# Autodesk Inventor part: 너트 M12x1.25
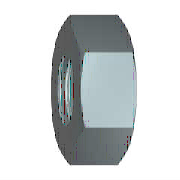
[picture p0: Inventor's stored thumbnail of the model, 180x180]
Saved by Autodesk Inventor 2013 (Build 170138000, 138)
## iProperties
IsCustomPart: 1
Created: 2012-02
Part Number: 너트 M12x1.25
Material: 강철, 연강
Description: 6각 너트
Document SubType Name: Modeling
Standard: KS B 1012
Designer: mduedu
Standards Organization: KS
Language: ko-KR
Size Designation: M12x1.25
Categories: <MemberInstance><Categories><Category DisplayName="조임쇠" InternalName="e4da775c-781d-43d5-af7c-5136215cf5a6" Mnemonic="FSTN"><Category DisplayName="너트" InternalN
Density: 1 g/cm^3
Author: mduedu
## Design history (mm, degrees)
sketch "스케치1"
  geometry: L1 (-10.97, 0)-(-5.485, 9.5); L2 (-5.485, 9.5)-(5.485, 9.5); L3 (5.485, 9.5)-(10.97, 0); L4 (10.97, 0)-(5.485, -9.5); L5 (5.485, -9.5)-(-5.485, -9.5); L6 (-5.485, -9.5)-(-10.97, 0); 2 further points
  constraints: 12 end point, 1 coincident, 1 horizontal, 11 other
  dimensions: "d0" = 21.93931 distance of L3.end L1.start (= 1.1547 x SW)
extrude "본체" new body sketch "스케치1" distance "d1" = 10 (= KOH); taper "d2" = 0 deg
sketch "스케치2"
  geometry: L1 (0, 5.485)-(0, 10.97) reference; L2 (0, 10.97)-(10, 10.97) reference; L3 (10, 5.485)-(10, 10.97) reference; L4 (-2, 0)-(12, 0) reference; L5 (0.849, 10.97)-(0, 9.5); L6 (9.151, 10.97)-(10, 9.5)
  constraints: 4 end point, 4 point on line
  dimensions: "d3" = 30 deg angle of L1 L5 (= ANG1); "d4" = 30 deg angle of L3 L6 (= ANG2); "d5" = 19 diameter of L5.end L4 (= SW0); "d6" = 19 diameter of L6.end L4 (= SW01)
revolve "모따기1" sketch "스케치2" stored, may be unused: angle "d7" = 90 deg
sketch "스케치3"
  geometry: A1 r 9.5 centre (0, 0) between (-4.75, -8.227) and (4.75, -8.227) reference; 1 further point
  constraints: 1 coincident
hole "스레드" sketch "스케치3" at (0, 0) diameter "d25" = 10.647; stored, may be unused: countersink angle "d29" = 82 deg, drill point angle "d31" = 118 deg; dims "d26" = 6, "d27" = 4, "d28" = 2, "d30" = 8
workaxis "Work Axis1"
workplane "Work Plane1"
body "Solid1"
chamfer "모따기2" distance "d8" = 0.67658 (= -0.5 x GD1 + 0.5 x NND); stored, may be unused: angle "d9" = 30 deg, second distance "d40" = 0.67658 (= -0.5 x GD1 + 0.5 x NND)
chamfer "모따기3" distance "d10" = 0.67658 (= -0.5 x GD1 + 0.5 x NND); stored, may be unused: angle "d11" = 30 deg, second distance "d41" = 0.67658 (= -0.5 x GD1 + 0.5 x NND)
other parameters: "ANG1" = 30 deg [user parameter; used in 1 equation term], "ANG2" = 30 deg [user parameter; used in 1 equation term], "NND" = 12 [user parameter; used in 4 equation terms], "KOH" = 10 [user parameter; used in 1 equation term], "SW" = 19 [user parameter; used in 4 equation terms], "SW0" = 19 (= SW) [user parameter; used in 1 equation term], "SW01" = 19 (= SW) [user parameter; used in 1 equation term], "GD1" = 10.64684 (computed from THREADDIA, PTC, TOA) [user parameter; used in 4 equation terms], "d13" = 0, "d14" = 0, "d39" = 0, "d42" = 0, "GUL" = 0.67658 (= 0.541266 x PTC) [user parameter], "TPU" = 8 (computed from PTC) [user parameter], "THREADDIA" = 12 [user parameter; used in 1 equation term], "TOA" = 30 deg [user parameter; used in 1 equation term], "PTC" = 1.25 [user parameter; used in 4 equation terms], "E0" = 21.945 (= 1.155 x SW) [user parameter], "GAL" = 0.67658 (= 0.541266 x PTC) [user parameter]
